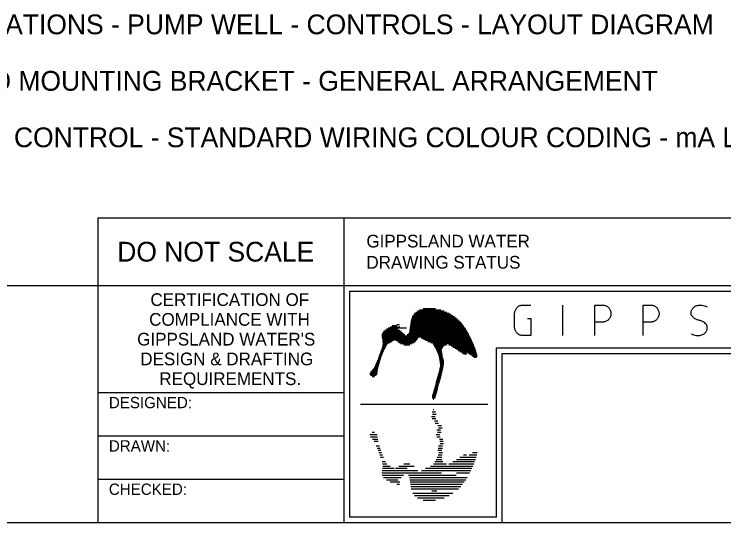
# Model space of a CAD drawing. Extents: x 0 to 841, y 0 to 594.
# Drawn here: x 577.7 to 703.2, y 15 to 105.1 of the extents above; entities that cross this region are included whole.
import ezdxf

# ---------------------------------------------------------------- set-up
doc = ezdxf.new("R2010")
doc.units = 0
doc.layers.add('A1BORDER', color=7, linetype='Continuous')
doc.layers.add('Level 1', color=7, linetype='Continuous')

msp = doc.modelspace()

# ---------------------------------------------------------------- linework, layer by layer
at = {"layer": 'A1BORDER'}
for p, q in [((592.5, 69), (592.5, 15)), ((592.5, 69), (829, 69)), ((636, 69), (636, 15)), ((28, 57), (829, 57)), ((637, 56), (788, 56)), ((637, 56), (637, 16)), ((650.01, 52.92), (652.2, 52.92)), ((648.12, 51.52), (655.59, 51.52)), ((648.23, 51.72), (655.31, 51.72)), ((648.37, 51.92), (655, 51.92)), ((648.53, 52.12), (654.64, 52.12)), ((648.74, 52.32), (654.24, 52.32)), ((649.02, 52.52), (653.76, 52.52)), ((649.39, 52.72), (653.15, 52.72)), ((647.81, 50.32), (656.86, 50.32)), ((647.85, 50.52), (656.69, 50.52)), ((647.88, 50.72), (656.5, 50.72)), ((647.91, 50.92), (656.3, 50.92)), ((647.96, 51.12), (656.08, 51.12)), ((648.03, 51.32), (655.85, 51.32)), ((643.26, 49.12), (645.9, 49.12)), ((643.54, 49.32), (645.57, 49.32)), ((643.85, 49.52), (647.09, 49.52)), ((644.18, 49.72), (645.89, 49.72)), ((644.54, 49.92), (645.36, 49.92)), ((645.37, 50.12), (645.86, 50.12)), ((647.63, 49.12), (657.68, 49.12)), ((647.66, 49.32), (657.57, 49.32)), ((647.69, 49.52), (657.44, 49.52)), ((647.71, 49.72), (657.31, 49.72)), ((647.75, 49.92), (657.17, 49.92)), ((647.78, 50.12), (657.02, 50.12)), ((642.73, 48.12), (658.25, 48.12)), ((642.74, 47.92), (658.35, 47.92)), ((642.75, 48.32), (646.79, 48.32)), ((642.79, 47.72), (649.08, 47.72)), ((642.81, 48.52), (646.55, 48.52)), ((642.9, 48.72), (646.37, 48.72)), ((643.04, 48.92), (646.16, 48.92)), ((647.19, 48.32), (658.14, 48.32)), ((647.42, 48.52), (658.03, 48.52)), ((647.54, 48.72), (657.92, 48.72)), ((647.61, 48.92), (657.8, 48.92)), ((649.72, 47.72), (658.45, 47.72)), ((642.83, 47.52), (648.95, 47.52)), ((642.85, 47.31), (644.88, 47.31)), ((642.87, 47.12), (644.57, 47.12)), ((642.87, 46.52), (643.6, 46.52)), ((642.88, 46.92), (644.23, 46.92)), ((642.88, 46.72), (643.83, 46.72)), ((645.14, 47.31), (648.83, 47.31)), ((645.49, 47.12), (648.67, 47.12)), ((645.76, 46.92), (648.42, 46.92)), ((646.05, 46.72), (648.11, 46.72)), ((646.62, 46.52), (647.67, 46.52)), ((650.12, 47.52), (658.55, 47.52)), ((650.48, 47.31), (658.64, 47.31)), ((650.87, 47.12), (658.73, 47.12)), ((651.36, 46.92), (658.82, 46.92)), ((651.76, 46.72), (658.9, 46.72)), ((651.88, 46.52), (654.15, 46.52)), ((654.57, 46.52), (658.99, 46.52)), ((642.5, 45.32), (643, 45.32)), ((642.57, 45.52), (643.1, 45.52)), ((642.65, 45.72), (643.2, 45.72)), ((642.72, 45.92), (643.3, 45.92)), ((642.79, 46.12), (643.4, 46.12)), ((642.84, 46.32), (643.5, 46.32)), ((651.99, 46.32), (653.71, 46.32)), ((652.1, 46.12), (653.52, 46.12)), ((652.2, 45.92), (653.4, 45.92)), ((652.31, 45.72), (653.33, 45.72)), ((652.41, 45.52), (653.31, 45.52)), ((652.5, 45.32), (653.34, 45.32)), ((655, 46.32), (659.07, 46.32)), ((655.31, 46.12), (659.14, 46.12)), ((655.62, 45.92), (659.22, 45.92)), ((655.93, 45.72), (659.29, 45.72)), ((656.24, 45.52), (659.35, 45.52)), ((656.55, 45.32), (659.42, 45.32)), ((663, 46), (788, 46)), ((663, 16), (663, 46)), ((642.06, 44.12), (642.55, 44.12)), ((642.13, 44.32), (642.62, 44.32)), ((642.21, 44.52), (642.69, 44.52)), ((642.28, 44.72), (642.76, 44.72)), ((642.35, 44.92), (642.83, 44.92)), ((642.43, 45.12), (642.9, 45.12)), ((652.6, 45.12), (653.38, 45.12)), ((652.69, 44.92), (653.41, 44.92)), ((652.78, 44.72), (653.44, 44.72)), ((652.83, 44.52), (653.48, 44.52)), ((652.86, 44.32), (653.53, 44.32)), ((652.89, 44.12), (653.57, 44.12)), ((656.86, 45.12), (657.74, 45.12)), ((657.17, 44.92), (657.68, 44.92)), ((657.51, 44.72), (657.54, 44.72)), ((657.91, 45.12), (659.48, 45.12)), ((658.19, 44.92), (659.54, 44.92)), ((658.47, 44.72), (659.59, 44.72)), ((658.75, 44.52), (659.58, 44.52)), ((659.02, 44.32), (659.47, 44.32)), ((664, 45), (829, 45)), ((664, 15), (664, 45)), ((641.46, 42.72), (642.15, 42.72)), ((641.55, 42.92), (642.2, 42.92)), ((641.64, 43.12), (642.25, 43.12)), ((641.73, 43.32), (642.3, 43.32)), ((641.82, 43.51), (642.35, 43.51)), ((641.91, 43.72), (642.41, 43.72)), ((641.99, 43.92), (642.48, 43.92)), ((652.91, 43.92), (653.62, 43.92)), ((652.94, 43.72), (653.67, 43.72)), ((652.97, 43.51), (653.71, 43.51)), ((653, 43.32), (653.69, 43.32)), ((653.02, 43.12), (653.67, 43.12)), ((653.03, 42.72), (653.61, 42.72)), ((653.05, 42.92), (653.64, 42.92)), ((640.63, 41.52), (641.93, 41.52)), ((640.73, 41.72), (641.95, 41.72)), ((640.9, 41.92), (641.97, 41.92)), ((641.1, 42.12), (642, 42.12)), ((641.25, 42.31), (642.04, 42.31)), ((641.37, 42.52), (642.09, 42.52)), ((652.74, 41.52), (653.37, 41.52)), ((652.79, 41.72), (653.41, 41.72)), ((652.85, 41.92), (653.45, 41.92)), ((652.9, 42.12), (653.49, 42.12)), ((652.95, 42.31), (653.53, 42.31)), ((652.99, 42.52), (653.57, 42.52)), ((640.62, 41.32), (641.88, 41.32)), ((640.72, 41.12), (641.73, 41.12)), ((641.03, 40.92), (641.43, 40.92)), ((652.41, 40.32), (653.04, 40.32)), ((652.47, 40.52), (653.1, 40.52)), ((652.52, 40.72), (653.15, 40.72)), ((652.57, 40.92), (653.2, 40.92)), ((652.63, 41.12), (653.26, 41.12)), ((652.68, 41.32), (653.31, 41.32)), ((652.03, 38.92), (652.66, 38.92)), ((652.09, 39.12), (652.72, 39.12)), ((652.14, 39.32), (652.77, 39.32)), ((652.2, 39.52), (652.82, 39.52)), ((652.25, 39.72), (652.88, 39.72)), ((652.3, 39.92), (652.93, 39.92)), ((652.36, 40.12), (652.99, 40.12)), ((636, 38), (592.5, 38)), ((651.71, 37.72), (652.34, 37.72)), ((651.76, 37.92), (652.39, 37.92)), ((651.82, 38.12), (652.44, 38.12)), ((651.87, 38.32), (652.5, 38.32)), ((651.92, 38.52), (652.55, 38.52)), ((651.98, 38.72), (652.61, 38.72)), ((651.63, 37.32), (652.23, 37.32)), ((651.64, 37.12), (652.17, 37.12)), ((651.65, 37.52), (652.28, 37.52)), ((651.79, 36.92), (651.9, 36.92)), ((638.93, 35.98), (661.47, 35.98)), ((651.63, 34.64), (652.23, 34.64)), ((651.71, 34.24), (652.34, 34.24)), ((651.79, 35.04), (651.9, 35.04)), ((651.54, 33.84), (652.17, 33.84)), ((651.65, 33.44), (652.28, 33.44)), ((652.03, 33.04), (652.66, 33.04)), ((652.14, 32.64), (652.77, 32.64)), ((652.47, 31.44), (653.1, 31.44)), ((652.66, 32.24), (653.29, 32.24)), ((652.77, 31.84), (653.4, 31.84)), ((636, 30.34), (592.5, 30.34)), ((640.62, 30.64), (641.88, 30.64)), ((640.73, 30.24), (641.95, 30.24)), ((641.03, 31.04), (641.43, 31.04)), ((652.34, 30.64), (652.97, 30.64)), ((652.45, 30.24), (653.07, 30.24)), ((652.57, 31.04), (653.2, 31.04)), ((641.1, 29.84), (642, 29.84)), ((641.37, 29.44), (642.09, 29.44)), ((652.9, 29.84), (653.49, 29.84)), ((652.99, 29.44), (653.57, 29.44)), ((653.05, 29.04), (653.64, 29.04)), ((641.73, 28.64), (642.3, 28.64)), ((641.91, 28.24), (642.41, 28.24)), ((642.06, 27.84), (642.55, 27.84)), ((652.66, 27.84), (653.35, 27.84)), ((652.72, 28.24), (653.44, 28.24)), ((652.77, 28.64), (653.46, 28.64)), ((642.21, 27.44), (642.69, 27.44)), ((642.35, 27.04), (642.83, 27.04)), ((642.5, 26.64), (643, 26.64)), ((652.5, 26.64), (653.34, 26.64)), ((652.69, 27.04), (653.41, 27.04)), ((652.83, 27.44), (653.48, 27.44)), ((656.55, 26.64), (659.42, 26.64)), ((657.17, 27.04), (657.68, 27.04)), ((658.19, 27.04), (659.54, 27.04)), ((658.75, 27.44), (659.58, 27.44)), ((642.79, 25.84), (643.4, 25.84)), ((642.87, 25.44), (643.6, 25.44)), ((646.62, 25.44), (647.67, 25.44)), ((651.88, 25.44), (654.15, 25.44)), ((652.1, 25.84), (653.52, 25.84)), ((652.31, 26.24), (653.33, 26.24)), ((654.57, 25.44), (658.99, 25.44)), ((655.31, 25.84), (659.14, 25.84)), ((655.93, 26.24), (659.29, 26.24)), ((642.79, 24.24), (649.08, 24.24)), ((642.85, 24.65), (644.88, 24.65)), ((642.88, 25.04), (644.23, 25.04)), ((645.14, 24.65), (647.18, 24.65)), ((645.76, 25.04), (648.42, 25.04)), ((649.72, 24.24), (658.45, 24.24)), ((650.48, 24.65), (658.64, 24.65)), ((651.36, 25.04), (658.82, 25.04)), ((636, 22.67), (592.5, 22.67)), ((642.73, 23.84), (653.27, 23.84)), ((642.81, 23.44), (646.55, 23.44)), ((643.04, 23.04), (646.16, 23.04)), ((643.54, 22.64), (645.57, 22.64)), ((647.42, 23.44), (655.89, 23.44)), ((647.61, 23.04), (657.8, 23.04)), ((647.66, 22.64), (657.57, 22.64)), ((655.94, 23.84), (658.25, 23.84)), ((644.18, 22.24), (645.89, 22.24)), ((645.37, 21.84), (645.86, 21.84)), ((647.71, 22.24), (657.31, 22.24)), ((647.78, 21.84), (657.02, 21.84)), ((647.85, 21.44), (656.69, 21.44)), ((647.91, 21.04), (656.3, 21.04)), ((648.23, 20.24), (655.31, 20.24)), ((651.57, 20.64), (652.44, 20.64)), ((648.53, 19.84), (654.64, 19.84)), ((649.02, 19.44), (653.76, 19.44)), ((650.01, 19.04), (652.2, 19.04)), ((663, 16), (637, 16)), ((829, 15), (28, 15))]:
    msp.add_line(p, q, dxfattribs=at)
for points in [[(668.49, 51.15), (669.06, 51.15), (669.06, 48.16), (667.64, 48.16), (667.51, 48.16), (667.39, 48.18), (667.28, 48.21), (667.15, 48.25), (667.04, 48.3), (666.93, 48.36), (666.82, 48.43), (666.73, 48.51), (666.64, 48.6), (666.55, 48.7), (666.48, 48.8), (666.41, 48.91), (666.35, 49.02), (666.31, 49.14), (666.27, 49.27), (666.24, 49.39), (666.22, 49.52), (666.22, 49.66), (666.22, 52.05), (666.22, 52.18), (666.24, 52.31), (666.27, 52.43), (666.31, 52.56), (666.35, 52.67), (666.41, 52.79), (666.48, 52.9), (666.55, 53), (666.64, 53.1), (666.73, 53.19), (666.82, 53.27), (666.93, 53.34), (667.04, 53.4), (667.15, 53.45), (667.28, 53.49), (667.39, 53.52), (667.51, 53.54), (667.64, 53.54), (669.06, 53.54)], [(674.74, 48.16), (674.74, 53.54)], [(680.42, 48.16), (680.42, 53.54), (681.84, 53.54), (681.96, 53.54), (682.08, 53.52), (682.2, 53.49), (682.32, 53.45), (682.43, 53.4), (682.54, 53.34), (682.65, 53.27), (682.74, 53.19), (682.84, 53.1), (682.92, 53), (682.99, 52.9), (683.06, 52.79), (683.12, 52.67), (683.17, 52.56), (683.21, 52.43), (683.23, 52.31), (683.25, 52.18), (683.26, 52.05), (683.25, 51.91), (683.23, 51.78), (683.21, 51.66), (683.17, 51.53), (683.12, 51.42), (683.06, 51.3), (682.99, 51.19), (682.92, 51.09), (682.84, 50.99), (682.74, 50.9), (682.65, 50.82), (682.54, 50.75), (682.43, 50.69), (682.32, 50.64), (682.2, 50.6), (682.08, 50.57), (681.96, 50.55), (681.84, 50.55), (680.42, 50.55)], [(688.93, 48.16), (688.93, 53.54), (690.35, 53.54), (690.47, 53.54), (690.59, 53.52), (690.71, 53.49), (690.83, 53.45), (690.94, 53.4), (691.05, 53.34), (691.16, 53.27), (691.26, 53.19), (691.35, 53.1), (691.43, 53), (691.51, 52.9), (691.57, 52.79), (691.63, 52.67), (691.68, 52.56), (691.72, 52.43), (691.75, 52.31), (691.76, 52.18), (691.77, 52.05), (691.76, 51.91), (691.75, 51.78), (691.72, 51.66), (691.68, 51.53), (691.63, 51.42), (691.57, 51.3), (691.51, 51.19), (691.43, 51.09), (691.35, 50.99), (691.26, 50.9), (691.16, 50.82), (691.05, 50.75), (690.94, 50.69), (690.83, 50.64), (690.71, 50.6), (690.59, 50.57), (690.47, 50.55), (690.35, 50.55), (688.93, 50.55)], [(697.45, 48.46), (697.67, 48.36), (697.9, 48.27), (698.12, 48.21), (698.36, 48.17), (698.6, 48.16), (698.84, 48.16), (698.87, 48.16), (699.03, 48.18), (699.18, 48.21), (699.33, 48.26), (699.48, 48.32), (699.62, 48.4), (699.72, 48.46), (699.81, 48.53), (699.9, 48.61), (699.98, 48.69), (700.05, 48.78), (700.11, 48.88), (700.17, 48.99), (700.22, 49.09), (700.25, 49.21), (700.28, 49.32), (700.29, 49.36), (700.3, 49.44), (700.3, 49.52), (700.3, 49.61), (700.29, 49.69), (700.27, 49.77), (700.25, 49.86), (700.22, 49.93), (700.18, 50.01), (700.14, 50.09), (700.09, 50.15), (700.04, 50.21), (700.01, 50.25), (699.85, 50.39), (699.69, 50.51), (699.52, 50.61), (699.34, 50.7), (699.15, 50.78), (698.95, 50.83), (698.87, 50.85), (698.68, 50.9), (698.49, 50.96), (698.3, 51.04), (698.12, 51.14), (697.96, 51.26), (697.8, 51.39), (697.73, 51.45), (697.67, 51.51), (697.62, 51.57), (697.58, 51.64), (697.53, 51.71), (697.5, 51.79), (697.47, 51.87), (697.46, 51.95), (697.44, 52.04), (697.43, 52.12), (697.43, 52.21), (697.44, 52.29), (697.45, 52.35), (697.47, 52.46), (697.51, 52.58), (697.55, 52.69), (697.61, 52.79), (697.67, 52.89), (697.74, 52.99), (697.82, 53.07), (697.9, 53.15), (697.99, 53.23), (698.02, 53.24), (698.15, 53.33), (698.3, 53.4), (698.44, 53.45), (698.6, 53.5), (698.75, 53.52), (698.87, 53.54), (699.11, 53.55), (699.35, 53.53), (699.58, 53.49), (699.82, 53.43), (700.04, 53.35), (700.27, 53.25)]]:
    msp.add_lwpolyline(points, dxfattribs=at)

# ---------------------------------------------------------------- texts
for s, height, p in [('GIPPSLAND WATER', 2.25, (640, 63.75)), ('DO NOT SCALE', 3.5, (595.92, 61.25)), ('DRAWING STATUS', 2.25, (640, 60)), ('CERTIFICATION OF', 2.25, (601.79, 53.39)), ('COMPLIANCE WITH', 2.25, (601.57, 49.89)), ("GIPPSLAND WATER'S", 2.25, (599.45, 46.39)), ('DESIGN & DRAFTING', 2.25, (600, 42.89)), ('REQUIREMENTS.', 2.25, (603.37, 39.39)), ('DESIGNED:', 2, (594.44, 35.29)), ('DRAWN:', 2, (594.44, 27.62)), ('CHECKED:', 2, (594.44, 19.95))]:
    msp.add_text(s, height=height, dxfattribs=at).set_placement(p)
at = {"layer": 'Level 1'}
for s, height, p in [('STANDARD DRAWINGS - SEWERAGE PUMP STATIONS - PUMP WELL - CONTROLS - LAYOUT DIAGRAM', 3.5, (470, 101.5)), ('STANDARD DRAWINGS - TRIO E SERIES RADIO MOUNTING BRACKET - GENERAL ARRANGEMENT', 3.5, (470, 91.5)), ('STANDARD DRAWINGS - INSTRUMENTATION & CONTROL - STANDARD WIRING COLOUR CODING - mA LOOP TERMINAL WIRING', 3.49998, (470, 81.5))]:
    msp.add_text(s, height=height, dxfattribs=at).set_placement(p)

doc.saveas('drawing.dxf')
